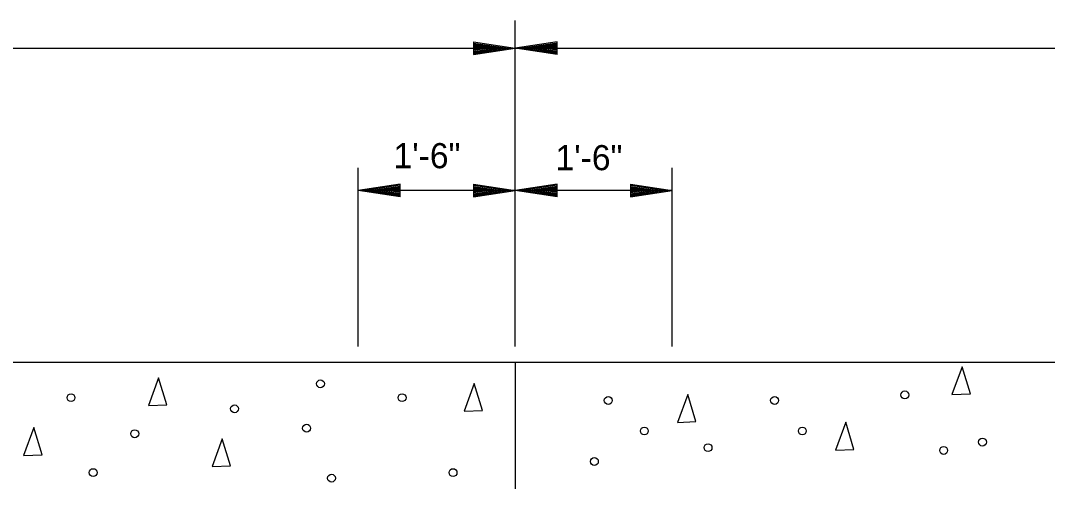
# Model space of a CAD drawing. Extents: x -149 to 1228740, y -106 to 152440.
# Drawn here: x -97.34 to -72.56, y 55.06 to 66.28 of the extents above; entities that cross this region are included whole.
import ezdxf

# ---------------------------------------------------------------- set-up
doc = ezdxf.new("R2010")
doc.units = 0
for name, color, linetype in [('R_Annotation', 7, 'Continuous'), ('R_Dimension', 7, 'Continuous'), ('R_Proposed Road', 7, 'Continuous')]:
    doc.layers.add(name, color=color, linetype=linetype)

msp = doc.modelspace()

# ---------------------------------------------------------------- linework, layer by layer
at = {"layer": 'R_Dimension'}
for p, q in [((-85.402, 58.412), (-85.402, 66.276)), ((-86.411, 65.759), (-85.401, 65.607)), ((-86.411, 65.759), (-86.411, 65.456)), ((-86.411, 65.734), (-85.57, 65.607)), ((-86.411, 65.708), (-85.744, 65.607)), ((-86.411, 65.683), (-85.911, 65.607)), ((-84.39, 65.759), (-85.401, 65.607)), ((-84.39, 65.734), (-85.231, 65.607)), ((-84.39, 65.708), (-85.059, 65.607)), ((-84.39, 65.683), (-84.89, 65.607)), ((-84.39, 65.456), (-84.39, 65.759)), ((-130.883, 65.608), (-85.402, 65.608)), ((-86.411, 65.658), (-86.083, 65.607)), ((-86.411, 65.633), (-86.252, 65.607)), ((-86.411, 65.456), (-85.401, 65.607)), ((-86.411, 65.559), (-86.083, 65.607)), ((-86.411, 65.506), (-85.744, 65.607)), ((-86.411, 65.481), (-85.57, 65.607)), ((-86.411, 65.532), (-85.911, 65.607)), ((-86.411, 65.585), (-86.252, 65.607)), ((-85.402, 65.608), (-43.711, 65.608)), ((-84.39, 65.456), (-85.401, 65.607)), ((-84.39, 65.481), (-85.231, 65.607)), ((-84.39, 65.506), (-85.059, 65.607)), ((-84.39, 65.532), (-84.89, 65.607)), ((-84.39, 65.658), (-84.718, 65.607)), ((-84.39, 65.559), (-84.718, 65.607)), ((-84.39, 65.633), (-84.549, 65.607)), ((-84.39, 65.585), (-84.549, 65.607)), ((-89.192, 58.412), (-89.192, 62.721)), ((-81.612, 58.412), (-81.612, 62.721)), ((-88.18, 62.328), (-89.191, 62.176)), ((-88.18, 62.302), (-89.021, 62.176)), ((-88.18, 62.277), (-88.85, 62.176)), ((-88.18, 62.252), (-88.68, 62.176)), ((-88.18, 62.227), (-88.508, 62.176)), ((-88.18, 62.024), (-88.18, 62.328)), ((-86.411, 62.328), (-85.401, 62.176)), ((-86.411, 62.328), (-86.411, 62.024)), ((-86.411, 62.302), (-85.57, 62.176)), ((-86.411, 62.277), (-85.744, 62.176)), ((-86.411, 62.252), (-85.911, 62.176)), ((-86.411, 62.227), (-86.083, 62.176)), ((-84.39, 62.328), (-85.401, 62.176)), ((-84.39, 62.302), (-85.231, 62.176)), ((-84.39, 62.277), (-85.059, 62.176)), ((-84.39, 62.252), (-84.89, 62.176)), ((-84.39, 62.227), (-84.718, 62.176)), ((-84.39, 62.024), (-84.39, 62.328)), ((-82.621, 62.328), (-81.611, 62.176)), ((-82.621, 62.328), (-82.621, 62.024)), ((-82.621, 62.302), (-81.78, 62.176)), ((-82.621, 62.277), (-81.954, 62.176)), ((-82.621, 62.252), (-82.121, 62.176)), ((-82.621, 62.227), (-82.293, 62.176)), ((-85.402, 62.177), (-89.192, 62.177)), ((-88.18, 62.024), (-89.191, 62.176)), ((-88.18, 62.05), (-89.021, 62.176)), ((-88.18, 62.075), (-88.85, 62.176)), ((-88.18, 62.1), (-88.68, 62.176)), ((-88.18, 62.128), (-88.508, 62.176)), ((-88.18, 62.201), (-88.339, 62.176)), ((-88.18, 62.153), (-88.339, 62.176)), ((-86.411, 62.201), (-86.252, 62.176)), ((-86.411, 62.024), (-85.401, 62.176)), ((-86.411, 62.128), (-86.083, 62.176)), ((-86.411, 62.075), (-85.744, 62.176)), ((-86.411, 62.05), (-85.57, 62.176)), ((-86.411, 62.1), (-85.911, 62.176)), ((-86.411, 62.153), (-86.252, 62.176)), ((-81.612, 62.177), (-85.402, 62.177)), ((-84.39, 62.024), (-85.401, 62.176)), ((-84.39, 62.05), (-85.231, 62.176)), ((-84.39, 62.075), (-85.059, 62.176)), ((-84.39, 62.1), (-84.89, 62.176)), ((-84.39, 62.128), (-84.718, 62.176)), ((-84.39, 62.201), (-84.549, 62.176)), ((-84.39, 62.153), (-84.549, 62.176)), ((-82.621, 62.201), (-82.462, 62.176)), ((-82.621, 62.024), (-81.611, 62.176)), ((-82.621, 62.128), (-82.293, 62.176)), ((-82.621, 62.075), (-81.954, 62.176)), ((-82.621, 62.05), (-81.78, 62.176)), ((-82.621, 62.1), (-82.121, 62.176)), ((-82.621, 62.153), (-82.462, 62.176))]:
    msp.add_line(p, q, dxfattribs=at)
at = {"layer": 'R_Proposed Road'}
for p, q in [((-130.883, 58.034), (-89.192, 58.034)), ((-89.192, 58.034), (-43.711, 58.034)), ((-85.402, 58.034), (-85.402, 54.98))]:
    msp.add_line(p, q, dxfattribs=at)
for points in [[(-74.617, 57.924), (-74.862, 57.254), (-74.417, 57.272), (-74.617, 57.924)], [(-94.012, 57.658), (-94.254, 56.989), (-93.81, 57.006), (-94.012, 57.658)], [(-86.389, 57.522), (-86.634, 56.852), (-86.189, 56.87), (-86.389, 57.522)], [(-81.239, 57.256), (-81.484, 56.584), (-81.039, 56.602), (-81.239, 57.256)], [(-77.426, 56.587), (-77.671, 55.915), (-77.227, 55.932), (-77.426, 56.587)], [(-97.021, 56.456), (-97.266, 55.783), (-96.821, 55.801), (-97.021, 56.456)], [(-92.473, 56.188), (-92.718, 55.516), (-92.273, 55.533), (-92.473, 56.188)]]:
    msp.add_lwpolyline(points, dxfattribs=at)
for centre in [(-90.101, 57.514), (-96.121, 57.179), (-88.131, 57.179), (-75.998, 57.246), (-92.175, 56.911), (-83.156, 57.112), (-79.142, 57.112), (-90.436, 56.443), (-94.583, 56.309), (-82.286, 56.376), (-78.473, 56.376), (-80.747, 55.974), (-74.125, 56.108), (-75.062, 55.907), (-83.49, 55.64), (-95.586, 55.372), (-89.834, 55.238), (-86.901, 55.372)]:
    msp.add_circle(centre, 0.0947, dxfattribs=at)

# ---------------------------------------------------------------- texts
at = {"layer": 'R_Annotation'}
for p in [(-88.337, 62.714), (-84.428, 62.666)]:
    msp.add_text('1\'-6"', height=0.6065, dxfattribs=at).set_placement(p)

doc.saveas('drawing.dxf')
